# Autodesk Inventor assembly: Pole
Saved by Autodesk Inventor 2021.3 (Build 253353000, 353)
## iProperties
Created: 2022-04
Part Number: Pole
Document SubType Name: Assembly
Designer: Administrator
Title: Pole v12
Author: Administrator
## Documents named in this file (2)
- c:\worker\convert-fusion-r02\tmp\job-1\57\output\files\f9e42cba-e390-44b0-9630-f24d5638462a\Pole v12.iam
- c:\worker\convert-fusion-r02\tmp\job-1\57\output\files\f9e42cba-e390-44b0-9630-f24d5638462a\Component1_2.ipt
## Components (1 placed, 1 different names)
1. Component1:1
